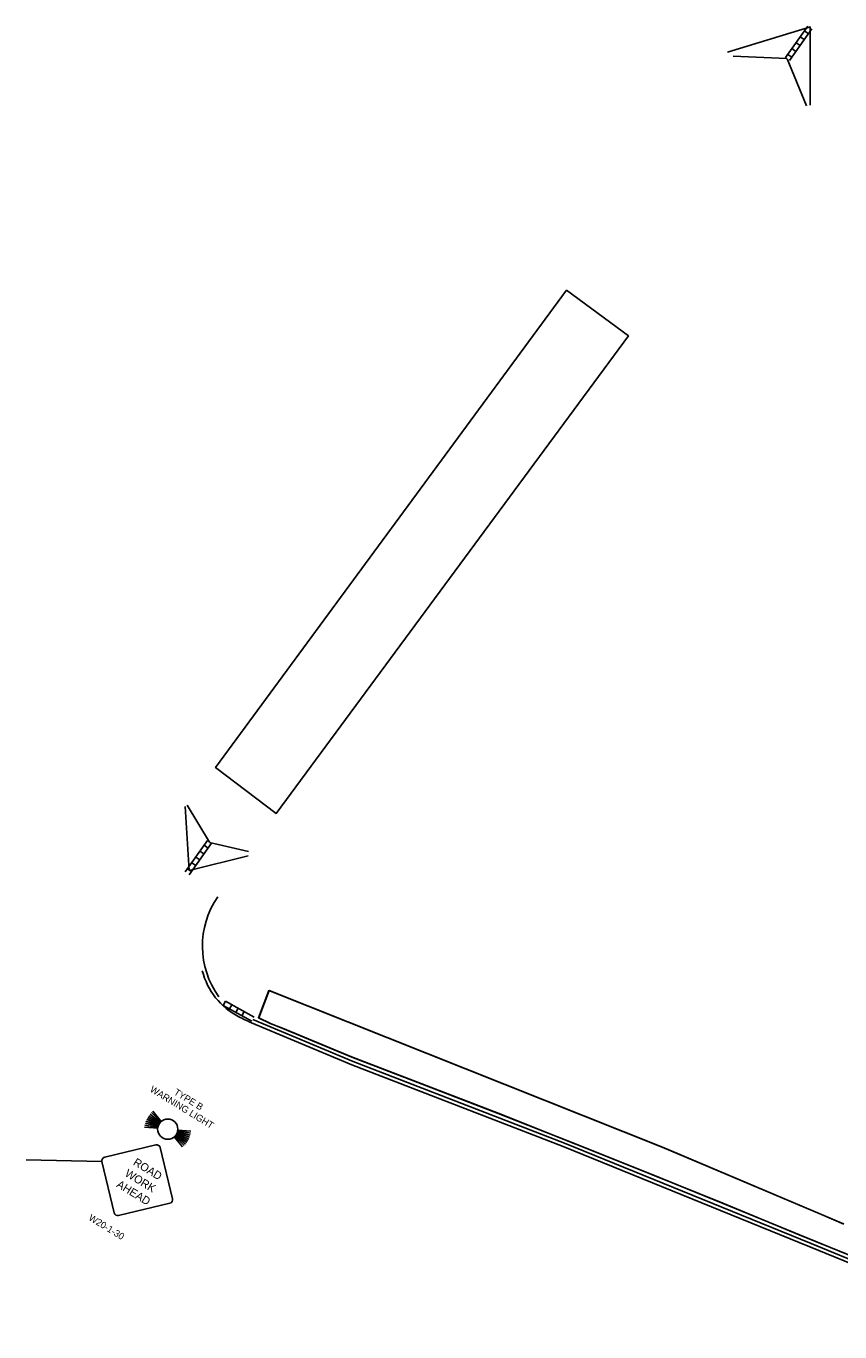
# Model space of a CAD drawing. Extents: x 1324973 to 1326617, y 459576 to 460945.
# Drawn here: x 1324973 to 1325311, y 459733 to 460276 of the extents above; entities that cross this region are included whole.
import ezdxf

# ---------------------------------------------------------------- set-up
doc = ezdxf.new("R2010")
doc.units = 0
for name, color, linetype in [('BR_P_Beam_Centerline', 7, 'Continuous'), ('BR_P_Slab_Object', 7, 'Continuous'), ('BR_P_Sub_Foot_Object', 7, 'Continuous'), ('BR_X_Dia_Text', 7, 'Continuous'), ('BR_X_Slab_Object', 7, 'Continuous'), ('BR_X_Sub_Foot_Object', 7, 'Continuous'), ('BR_X_Sub_Object', 7, 'Continuous'), ('SC_Scratch17', 7, 'Continuous')]:
    doc.layers.add(name, color=color, linetype=linetype)

msp = doc.modelspace()

# ---------------------------------------------------------------- linework, layer by layer
at = {"layer": 'BR_P_Beam_Centerline'}
for p, q in [((1325299.03, 460275.92), (1325264.58, 460265.35)), ((1325298.93, 460275.93), (1325299, 460243.4)), ((1325040.48, 459924.82), (1325038.8, 459951.41)), ((1325040.48, 459924.82), (1325064.93, 459930.88))]:
    msp.add_line(p, q, dxfattribs=at)
msp.add_arc((1325082.05, 459893.31), 36.11, 145.3775, 215.8445, dxfattribs=at)
at = {"layer": 'BR_P_Sub_Foot_Object'}
for p, q in [((1325066.35, 459861.42), (1325108.12, 459843.94)), ((1325066.35, 459861.42), (1325108.12, 459843.94)), ((1325108.12, 459843.94), (1325196.09, 459809.94)), ((1325108.12, 459843.94), (1325196.09, 459809.94)), ((1325196.09, 459809.94), (1325298.82, 459768.19)), ((1325196.09, 459809.94), (1325298.82, 459768.19)), ((1325298.82, 459768.19), (1325384.64, 459732.74)), ((1325298.82, 459768.19), (1325384.64, 459732.74))]:
    msp.add_line(p, q, dxfattribs=at)
for centre, radius, start, end in [((1325074.94, 459890.5), 30, 194.4882, 242.3964), ((1325092.92, 459924.9), 68.81, 242.3964, 247.2879), ((1325092.92, 459924.9), 68.81, 242.3964, 247.2879)]:
    msp.add_arc(centre, radius, start, end, dxfattribs=at)
at = {"layer": 'BR_X_Dia_Text'}
for p, q in [((1325298.03, 460276.25), (1325288.74, 460263.15)), ((1325299.66, 460275.1), (1325290.37, 460262)), ((1325294.76, 460268.18), (1325293.13, 460269.34)), ((1325296.49, 460270.63), (1325294.86, 460271.79)), ((1325298.25, 460273.08), (1325296.62, 460274.24)), ((1325291.29, 460263.29), (1325289.66, 460264.44)), ((1325293.02, 460265.74), (1325291.39, 460266.89)), ((1325048.07, 459937.29), (1325038.79, 459924.19)), ((1325049.71, 459936.14), (1325040.42, 459923.03)), ((1325046.54, 459931.67), (1325044.91, 459932.82)), ((1325048.27, 459934.12), (1325046.64, 459935.27)), ((1325043.14, 459926.88), (1325041.51, 459928.04)), ((1325044.8, 459929.22), (1325043.17, 459930.38)), ((1325041.33, 459924.33), (1325039.7, 459925.48)), ((1325055.53, 459870.34), (1325054.56, 459868.59)), ((1325054.56, 459868.59), (1325066.45, 459862.01)), ((1325055.08, 459867.88), (1325055.08, 459867.88)), ((1325055.53, 459870.34), (1325067.42, 459863.76)), ((1325056.05, 459869.63), (1325056.05, 459869.63)), ((1325058.16, 459868.89), (1325057.19, 459867.14)), ((1325060.78, 459867.43), (1325059.81, 459865.68)), ((1325063.29, 459866.04), (1325062.33, 459864.29))]:
    msp.add_line(p, q, dxfattribs=at)
at = {"layer": 'BR_X_Slab_Object'}
for points in [[(1325005.25, 459805.48), (1325026.53, 459810.57)], [(1325028.41, 459809.42), (1325033.5, 459788.14)], [(1325009.19, 459782.32), (1325004.1, 459803.6)], [(1325032.35, 459786.26), (1325011.07, 459781.17)]]:
    msp.add_lwpolyline(points, dxfattribs=at)
for centre, start, end in [((1325026.89, 459809.05), 13.4601, 103.4601), ((1325005.62, 459803.96), 103.4601, 193.4601), ((1325031.98, 459787.78), 283.4601, 13.4601), ((1325010.71, 459782.69), 193.4601, 283.4601)]:
    msp.add_arc(centre, 1.56, start, end, dxfattribs=at)
at = {"layer": 'BR_X_Sub_Foot_Object'}
for points in [[(1325076.68, 459948.57), (1325051.44, 459967.62), (1325197.54, 460166.28), (1325223.3, 460147.28), (1325076.68, 459948.57)], [(1325076.68, 459948.57), (1325051.44, 459967.62), (1325197.54, 460166.28), (1325223.3, 460147.28), (1325076.68, 459948.57)], [(1325326.96, 459759.9), (1325294.37, 459773.19), (1325262.59, 459786.26), (1325232.61, 459798.43), (1325201.39, 459810.92), (1325169, 459823.74), (1325137.33, 459835.95), (1325107.98, 459847.16), (1325079.26, 459859.14), (1325074.2, 459861.17), (1325069.26, 459863.49), (1325073.61, 459874.82), (1325237.31, 459809.69), (1325303.61, 459781.59), (1325312.85, 459777.67)], [(1325327.08, 459759.85), (1325294.49, 459773.14), (1325262.71, 459786.21), (1325232.73, 459798.38), (1325201.51, 459810.88), (1325169.12, 459823.7), (1325137.45, 459835.9), (1325108.1, 459847.12), (1325079.38, 459859.09), (1325074.32, 459861.12), (1325069.38, 459863.44), (1325073.73, 459874.77), (1325237.43, 459809.64), (1325303.73, 459781.54), (1325312.97, 459777.62)]]:
    msp.add_lwpolyline(points, dxfattribs=at)
msp.add_lwpolyline([(1325223.3, 460147.28), (1325197.54, 460166.28), (1325051.44, 459967.62), (1325076.68, 459948.57)], close=True, dxfattribs=at)
at = {"layer": 'BR_X_Sub_Object'}
for p, q in [((1325024.71, 459823.99), (1325028.55, 459820.11)), ((1325025.33, 459824.55), (1325028.83, 459820.36)), ((1325022.01, 459818.84), (1325027.38, 459817.88)), ((1325022.19, 459819.67), (1325027.46, 459818.24)), ((1325022.45, 459820.47), (1325027.57, 459818.58)), ((1325022.77, 459821.25), (1325027.71, 459818.92)), ((1325023.16, 459821.99), (1325027.88, 459819.25)), ((1325023.62, 459822.7), (1325028.08, 459819.55)), ((1325024.13, 459823.37), (1325028.31, 459819.84)), ((1325021.89, 459818.01), (1325027.33, 459817.52)), ((1325034.2, 459813.91), (1325037.7, 459809.72)), ((1325034.47, 459814.16), (1325038.32, 459810.28)), ((1325034.72, 459814.43), (1325038.89, 459810.9)), ((1325034.94, 459814.72), (1325039.41, 459811.57)), ((1325035.14, 459815.02), (1325039.86, 459812.28)), ((1325035.31, 459815.35), (1325040.25, 459813.02)), ((1325035.45, 459815.69), (1325040.58, 459813.8)), ((1325035.56, 459816.04), (1325040.83, 459814.6)), ((1325035.64, 459816.39), (1325041.02, 459815.43)), ((1325035.69, 459816.76), (1325041.13, 459816.26)), ((1324972.54, 459804.39), (1325004.1, 459803.6))]:
    msp.add_line(p, q, dxfattribs=at)
msp.add_circle((1325031.51, 459817.14), 4.2, dxfattribs=at)
at = {"layer": 'SC_Scratch17'}
for p, q in [((1325266.92, 460263.73), (1325289.28, 460262.72)), ((1325297.37, 460243.14), (1325289.36, 460262.65)), ((1325039.66, 459952.05), (1325048.92, 459936.54)), ((1325065.07, 459932.67), (1325048.94, 459936.49)), ((1325066.93, 459862.81), (1325108.68, 459845.33)), ((1325108.68, 459845.33), (1325196.64, 459811.34)), ((1325196.64, 459811.34), (1325299.39, 459769.58)), ((1325299.39, 459769.58), (1325385.23, 459734.12))]:
    msp.add_line(p, q, dxfattribs=at)

# ---------------------------------------------------------------- texts
at = {"layer": 'BR_P_Slab_Object'}
for s, p in [('WARNING LIGHT', (1325023.83, 459832.95)), ('TYPE B', (1325033.79, 459831.77)), ('W20-1-30', (1324998.31, 459779.49))]:
    msp.add_text(s, height=2.8, rotation=328.4601, dxfattribs=at).set_placement(p)
at = {"layer": 'BR_X_Slab_Object'}
for s, p in [('ROAD', (1325016.81, 459802.47)), ('WORK', (1325013.35, 459797.87)), ('AHEAD', (1325009.89, 459793.28))]:
    msp.add_text(s, height=3.332, rotation=328.4601, dxfattribs=at).set_placement(p)

doc.saveas('drawing.dxf')
